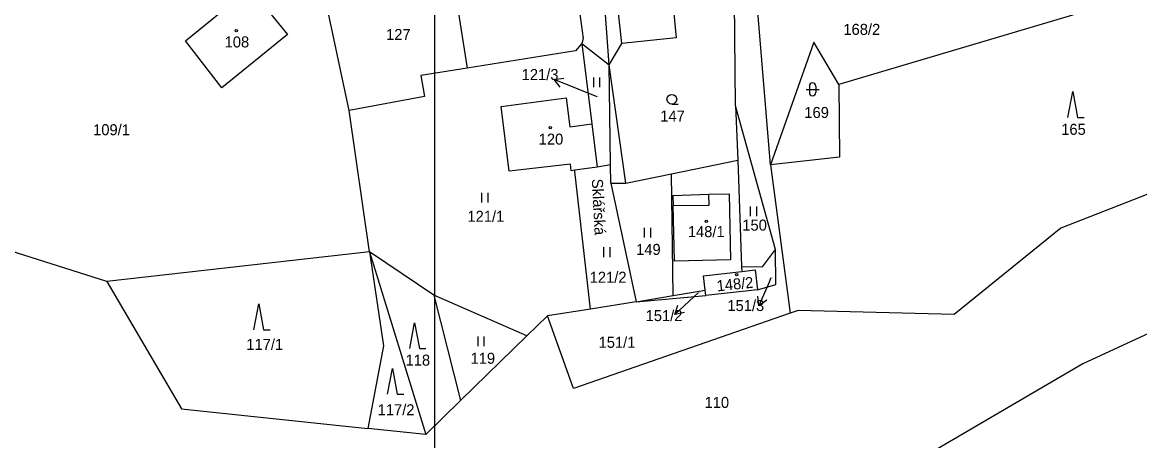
# Model space of a CAD drawing. Extents: x -670359 to -668019, y -978807 to -976674.
# Drawn here: x -670063.7 to -669891.1, y -977284.7 to -977220.1 of the extents above; entities that cross this region are included whole.
import ezdxf

# ---------------------------------------------------------------- set-up
doc = ezdxf.new("R2010")
doc.units = 0
for name, color, linetype in [('Hranice parcel', 7, 'Continuous'), ('ML1000', 7, 'Continuous'), ('Parcelní čísla', 7, 'Continuous'), ('Pop  PČ popisy', 7, 'Continuous'), ('Vnitřní kresba', 7, 'Continuous'), ('Značky budov', 7, 'Continuous'), ('Značky kultur', 7, 'Continuous')]:
    doc.layers.add(name, color=color, linetype=linetype)

msp = doc.modelspace()

# ---------------------------------------------------------------- linework, layer by layer
at = {"layer": 'Hranice parcel'}
for points in [[(-669979.85, -977202.18), (-669977.1, -977222.62)], [(-669998.63, -977204.37), (-669994.99, -977227.2)], [(-669953.54, -977233.03), (-669953.8, -977206.06)], [(-669973.08, -977226.71), (-669974.43, -977207.58)], [(-669963.9, -977210.16), (-669962.71, -977222.54)], [(-669948.13, -977242.11), (-669950.8, -977209.75)], [(-669971.1, -977223.39), (-669972.45, -977211.09)], [(-670038.5, -977223), (-670028.57, -977214.86)], [(-670028.57, -977214.86), (-670022.77, -977222.02)], [(-669892.61, -977216.37), (-669937.56, -977229.74)], [(-670013.23, -977233.75), (-670016.43, -977218.79)], [(-670022.77, -977222.02), (-670032.88, -977230.23)], [(-669962.71, -977222.54), (-669971.1, -977223.39)], [(-670032.88, -977230.23), (-670038.5, -977223)], [(-669977.27, -977223.41), (-669978.29, -977224.55)], [(-669977.1, -977222.62), (-669977.27, -977223.41)], [(-669977.27, -977223.41), (-669975.76, -977235.81)], [(-669977.27, -977223.41), (-669973.08, -977226.71)], [(-669941.43, -977223.21), (-669948.13, -977242.11)], [(-669937.56, -977229.74), (-669941.43, -977223.21)], [(-669978.29, -977224.55), (-669994.99, -977227.2)], [(-669994.99, -977227.2), (-670002.18, -977228.33)], [(-669972.86, -977242.12), (-669973.08, -977226.71)], [(-670002.18, -977228.33), (-670001.61, -977231.6)], [(-669937.56, -977229.74), (-669937.5, -977240.93)], [(-670001.61, -977231.6), (-670013.23, -977233.75)], [(-669989.74, -977233.11), (-669979.73, -977231.81)], [(-669979.73, -977231.81), (-669979.14, -977236.24)], [(-670010.11, -977255.58), (-670013.23, -977233.75)], [(-669988.49, -977243.13), (-669989.74, -977233.11)], [(-669947.38, -977255.2), (-669953.54, -977233.03)], [(-669953.54, -977233.03), (-669953.17, -977241.42)], [(-669979.14, -977236.24), (-669975.76, -977235.81)], [(-669975.76, -977235.81), (-669974.94, -977242.47)], [(-669963.43, -977243.51), (-669953.17, -977241.42)], [(-669953.17, -977241.42), (-669952.6, -977257.8)], [(-669937.5, -977240.93), (-669948.13, -977242.11)], [(-669979.02, -977242.01), (-669988.49, -977243.13)], [(-669978.91, -977243.05), (-669979.02, -977242.01)], [(-669978.38, -977242.97), (-669978.91, -977243.05)], [(-669974.94, -977242.47), (-669978.38, -977242.97)], [(-669975.96, -977264.38), (-669978.35, -977243.14), (-669978.38, -977242.97)], [(-669972.86, -977242.12), (-669974.94, -977242.47)], [(-669972.82, -977244.97), (-669972.86, -977242.12)], [(-669948.13, -977242.11), (-669945.09, -977265.04)], [(-669879.68, -977242.68), (-669903.28, -977251.92)], [(-669972.82, -977244.97), (-669970.51, -977244.96)], [(-669972.82, -977244.97), (-669968.89, -977263.29)], [(-669970.51, -977244.96), (-669963.43, -977243.51)], [(-669963.18, -977262.32), (-669963.43, -977243.51)], [(-670050.66, -977260.11), (-670096.49, -977245.64)], [(-669903.28, -977251.92), (-669919.77, -977265.25)], [(-669949.4, -977257.86), (-669947.38, -977255.2)], [(-669947.34, -977260.59), (-669947.38, -977255.2)], [(-670010.11, -977255.58), (-670050.66, -977260.11)], [(-670000.16, -977262.24), (-670010.11, -977255.58)], [(-670010.11, -977255.58), (-670001.38, -977283.75)], [(-670010.11, -977255.58), (-670007.92, -977270.07)], [(-669958.49, -977259.24), (-669952.58, -977258.58)], [(-669952.6, -977257.8), (-669949.4, -977257.86)], [(-669952.6, -977257.8), (-669952.58, -977258.58)], [(-669952.58, -977258.58), (-669950.52, -977258.35)], [(-669950.52, -977258.35), (-669950.17, -977261.42)], [(-670050.66, -977260.11), (-670039.14, -977279.77)], [(-669958.21, -977261.47), (-669958.49, -977259.24)], [(-669873.27, -977260.54), (-669899.87, -977272.82)], [(-669985.76, -977268.51), (-670000.16, -977262.24)], [(-670000.16, -977262.24), (-669996.01, -977278.51)], [(-669963.18, -977262.32), (-669958.21, -977261.47)], [(-669958.11, -977262.31), (-669958.21, -977261.47)], [(-669950.17, -977261.42), (-669958.11, -977262.31)], [(-669950.17, -977261.42), (-669947.34, -977260.59)], [(-669968.89, -977263.29), (-669975.96, -977264.38)], [(-669968.89, -977263.29), (-669958.11, -977262.31)], [(-669968.89, -977263.29), (-669963.18, -977262.32)], [(-669982.59, -977265.41), (-669985.76, -977268.51)], [(-669975.96, -977264.38), (-669982.59, -977265.41)], [(-669978.55, -977276.66), (-669982.59, -977265.41)], [(-669945.09, -977265.04), (-669978.55, -977276.66)], [(-669943.86, -977264.62), (-669945.09, -977265.04)], [(-669919.77, -977265.25), (-669943.86, -977264.62)], [(-669985.76, -977268.51), (-669996.01, -977278.51)], [(-670007.92, -977270.07), (-670010.33, -977282.81)], [(-669899.87, -977272.82), (-669928.04, -977289.3)], [(-669996.01, -977278.51), (-670001.38, -977283.75)], [(-670039.14, -977279.77), (-670010.33, -977282.81)], [(-670001.38, -977283.75), (-670010.33, -977282.81)]]:
    msp.add_lwpolyline(points, dxfattribs=at)
at = {"layer": 'ML1000'}
msp.add_lwpolyline([(-669375, -977000), (-669375, -977500), (-670000, -977500), (-670000, -977000)], close=True, dxfattribs=at)
at = {"layer": 'Parcelní čísla'}
for p, q in [((-669980.63, -977230.13), (-669981.56, -977228.95)), ((-669974.9, -977231.63), (-669977.85, -977230.44)), ((-669948.07, -977259.58), (-669948.35, -977260.24)), ((-669959.3, -977261.89), (-669959.97, -977262.51)), ((-669948.73, -977263.02), (-669949.93, -977263.91)), ((-669961.44, -977264.9), (-669962.9, -977265.23))]:
    msp.add_line(p, q, dxfattribs=at)
for points in [[(-669977.85, -977230.44), (-669981.56, -977228.95), (-669980.07, -977228.74)], [(-669948.35, -977260.24), (-669949.93, -977263.91), (-669950.11, -977262.42)], [(-669959.97, -977262.51), (-669962.9, -977265.23), (-669962.46, -977263.8)]]:
    msp.add_lwpolyline(points, dxfattribs=at)
at = {"layer": 'Vnitřní kresba'}
for points in [[(-669973.08, -977226.71), (-669971.1, -977223.39)], [(-669970.51, -977244.96), (-669973.08, -977226.71)], [(-669963.21, -977246.84), (-669957.66, -977246.68)], [(-669957.66, -977246.68), (-669954.51, -977246.59)], [(-669957.61, -977248.33), (-669957.66, -977246.68)], [(-669954.51, -977246.59), (-669954.3, -977256.78)], [(-669963.21, -977246.84), (-669963.17, -977248.43)], [(-669963.17, -977248.43), (-669957.61, -977248.33)], [(-669962.96, -977256.99), (-669963.17, -977248.43)], [(-669954.3, -977256.78), (-669962.96, -977256.99)]]:
    msp.add_lwpolyline(points, dxfattribs=at)
at = {"layer": 'Značky budov'}
for centre in [(-670030.68, -977221.41), (-669982.16, -977236.41), (-669958.06, -977250.83), (-669953.38, -977259.09)]:
    msp.add_circle(centre, 0.175, dxfattribs=at)
at = {"layer": 'Značky kultur'}
for p, q in [((-669975.49, -977228.64), (-669975.49, -977230.14)), ((-669974.49, -977230.14), (-669974.49, -977228.64)), ((-669942.64, -977230.48), (-669940.64, -977230.48)), ((-669942.14, -977229.98), (-669942.14, -977230.98)), ((-669941.14, -977229.98), (-669941.14, -977230.98)), ((-669963.38, -977232.75), (-669962.38, -977232.75)), ((-669992.78, -977246.45), (-669992.78, -977247.95)), ((-669991.78, -977247.95), (-669991.78, -977246.45)), ((-669951.26, -977248.55), (-669951.26, -977250.05)), ((-669950.26, -977250.05), (-669950.26, -977248.55)), ((-669967.65, -977251.83), (-669967.65, -977253.33)), ((-669966.65, -977253.33), (-669966.65, -977251.83)), ((-669973.93, -977254.86), (-669973.93, -977256.36)), ((-669972.93, -977256.36), (-669972.93, -977254.86)), ((-669993.37, -977268.63), (-669993.37, -977270.13)), ((-669992.37, -977270.13), (-669992.37, -977268.63))]:
    msp.add_line(p, q, dxfattribs=at)
for points in [[(-669902.19, -977234.8), (-669901.44, -977230.8), (-669900.69, -977234.8), (-669899.69, -977234.8)], [(-670027.95, -977267.57), (-670027.2, -977263.57), (-670026.45, -977267.57), (-670025.45, -977267.57)], [(-670003.87, -977270.49), (-670003.12, -977266.49), (-670002.37, -977270.49), (-670001.37, -977270.49)], [(-670007.29, -977277.54), (-670006.54, -977273.54), (-670005.79, -977277.54), (-670004.79, -977277.54)]]:
    msp.add_lwpolyline(points, dxfattribs=at)
for centre, radius in [((-670030.68, -977221.41), 0.175), ((-669963.38, -977232), 0.75), ((-669982.16, -977236.41), 0.175), ((-669958.06, -977250.83), 0.175), ((-669953.38, -977259.09), 0.175)]:
    msp.add_circle(centre, radius, dxfattribs=at)
for centre, start, end in [((-669941.64, -977229.98), 0, 180), ((-669941.64, -977230.98), 180, 0)]:
    msp.add_arc(centre, 0.5, start, end, dxfattribs=at)

# ---------------------------------------------------------------- texts
at = {"layer": 'Parcelní čísla'}
for s, height, p in [('168/2', 1.7, (-669936.88, -977222.07)), ('108', 1.7, (-670032.47, -977224.01)), ('127', 1.7, (-670007.53, -977222.86)), ('121/3', 1.7, (-669986.58, -977229.04)), ('121/3', 0.1, (-669975.08, -977231.63)), ('147', 1.7, (-669965.17, -977235.45)), ('169', 1.7, (-669942.91, -977234.9)), ('109/1', 1.7, (-670052.79, -977237.56)), ('165', 1.7, (-669903.23, -977237.5)), ('120', 1.7, (-669983.95, -977239.01)), ('121/1', 1.7, (-669994.96, -977250.92)), ('148/1', 1.7, (-669960.91, -977253.29)), ('150', 1.7, (-669952.49, -977252.28)), ('149', 1.7, (-669968.9, -977256.03)), ('121/2', 1.7, (-669976.07, -977260.33)), ('151/3', 0.1, (-669948.07, -977259.58)), ('151/2', 0.1, (-669959.3, -977261.89)), ('151/3', 1.7, (-669954.8, -977264.69)), ('151/2', 1.7, (-669967.43, -977266.25)), ('117/1', 1.7, (-670029.12, -977270.69)), ('151/1', 1.7, (-669974.7, -977270.37)), ('118', 1.7, (-670004.52, -977273.12)), ('119', 1.7, (-669994.48, -977272.83)), ('117/2', 1.7, (-670008.83, -977280.78)), ('110', 1.7, (-669958.33, -977279.65))]:
    msp.add_text(s, height=height, dxfattribs=at).set_placement(p)
msp.add_text('148/2', height=1.7, rotation=5.9314, dxfattribs=at).set_placement((-669956.36, -977261.67))
at = {"layer": 'Pop  PČ popisy'}
msp.add_text('Sklářská', height=1.7, rotation=272.8915, dxfattribs=at).set_placement((-669975.75, -977244.32))

doc.saveas('drawing.dxf')
